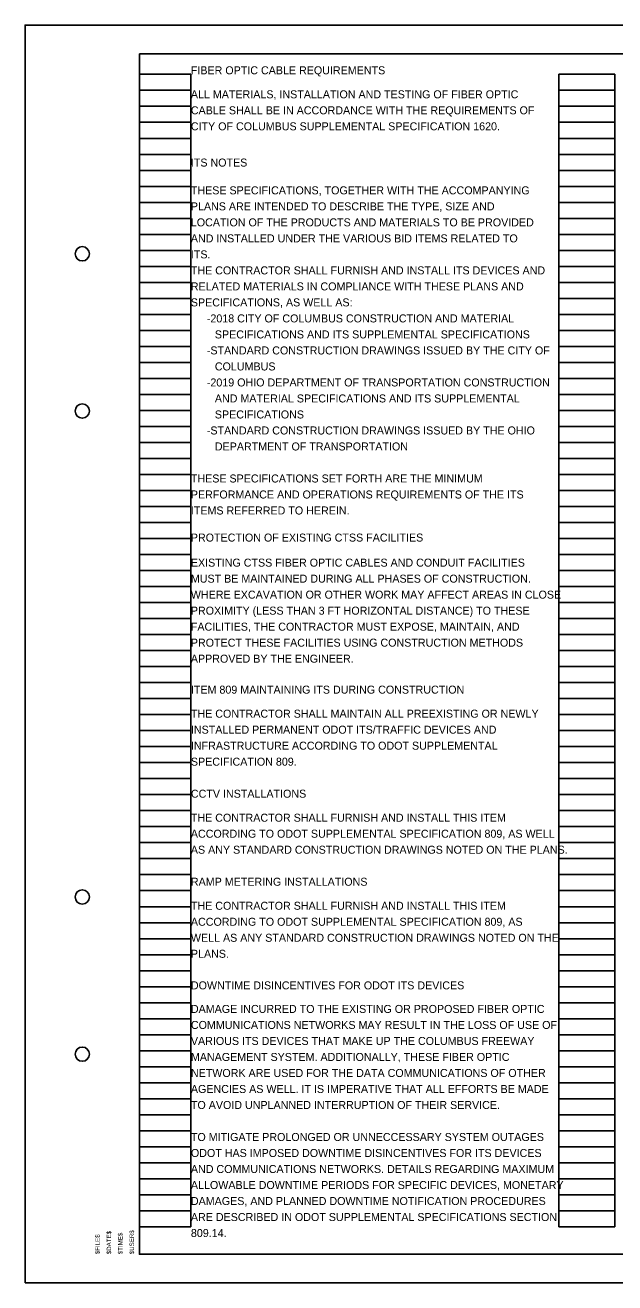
# Model space of a CAD drawing. Extents: x -36.9 to 49.6, y -47.1 to 37.
# Drawn here: x -0.51 to 9.81, y -7.51 to 14.49 of the extents above; entities that cross this region are included whole.
import ezdxf

# ---------------------------------------------------------------- set-up
doc = ezdxf.new("R2010")
doc.units = 0
for name, color, linetype in [('PF_P_Text', 7, 'Continuous'), ('SC_Scratch1', 7, 'Continuous'), ('SH_Cut_Line', 7, 'Continuous'), ('SH_Text', 7, 'Continuous'), ('TX_P_Misc', 7, 'Continuous')]:
    doc.layers.add(name, color=color, linetype=linetype)

msp = doc.modelspace()

# ---------------------------------------------------------------- linework, layer by layer
at = {"layer": 'PF_P_Text'}
msp.add_lwpolyline([(1.494, 13.992), (32.994, 13.992), (32.994, -7.008), (1.494, -7.008)], close=True, dxfattribs=at)
for centre in [(0.494, 10.492), (0.494, 7.742), (0.494, -0.758), (0.494, -3.508)]:
    msp.add_circle(centre, 0.125, dxfattribs=at)
at = {"layer": 'SC_Scratch1'}
for p, q in [((1.494, -6.528), (1.494, 13.632)), ((1.494, 13.632), (2.394, 13.632)), ((2.394, -6.528), (2.394, 13.632)), ((8.834, -6.528), (8.834, 13.632)), ((8.834, 13.632), (9.814, 13.632)), ((9.814, -6.528), (9.814, 13.632)), ((1.494, 13.352), (2.394, 13.352)), ((8.834, 13.352), (9.814, 13.352)), ((1.494, 13.072), (2.394, 13.072)), ((8.834, 13.072), (9.814, 13.072)), ((1.494, 12.792), (2.394, 12.792)), ((8.834, 12.792), (9.814, 12.792)), ((1.494, 12.512), (2.394, 12.512)), ((8.834, 12.512), (9.814, 12.512)), ((1.494, 12.232), (2.394, 12.232)), ((8.834, 12.232), (9.814, 12.232)), ((1.494, 11.952), (2.394, 11.952)), ((8.834, 11.952), (9.814, 11.952)), ((1.494, 11.672), (2.394, 11.672)), ((8.834, 11.672), (9.814, 11.672)), ((1.494, 11.392), (2.394, 11.392)), ((8.834, 11.392), (9.814, 11.392)), ((1.494, 11.112), (2.394, 11.112)), ((8.834, 11.112), (9.814, 11.112)), ((1.494, 10.832), (2.394, 10.832)), ((8.834, 10.832), (9.814, 10.832)), ((1.494, 10.552), (2.394, 10.552)), ((8.834, 10.552), (9.814, 10.552)), ((1.494, 10.272), (2.394, 10.272)), ((8.834, 10.272), (9.814, 10.272)), ((1.494, 9.992), (2.394, 9.992)), ((8.834, 9.992), (9.814, 9.992)), ((1.494, 9.712), (2.394, 9.712)), ((8.834, 9.712), (9.814, 9.712)), ((1.494, 9.432), (2.394, 9.432)), ((8.834, 9.432), (9.814, 9.432)), ((1.494, 9.152), (2.394, 9.152)), ((8.834, 9.152), (9.814, 9.152)), ((1.494, 8.872), (2.394, 8.872)), ((8.834, 8.872), (9.814, 8.872)), ((1.494, 8.592), (2.394, 8.592)), ((8.834, 8.592), (9.814, 8.592)), ((1.494, 8.312), (2.394, 8.312)), ((8.834, 8.312), (9.814, 8.312)), ((1.494, 8.032), (2.394, 8.032)), ((8.834, 8.032), (9.814, 8.032)), ((1.494, 7.752), (2.394, 7.752)), ((8.834, 7.752), (9.814, 7.752)), ((1.494, 7.472), (2.394, 7.472)), ((8.834, 7.472), (9.814, 7.472)), ((1.494, 7.192), (2.394, 7.192)), ((8.834, 7.192), (9.814, 7.192)), ((1.494, 6.912), (2.394, 6.912)), ((8.834, 6.912), (9.814, 6.912)), ((1.494, 6.632), (2.394, 6.632)), ((8.834, 6.632), (9.814, 6.632)), ((1.494, 6.352), (2.394, 6.352)), ((8.834, 6.352), (9.814, 6.352)), ((1.494, 6.072), (2.394, 6.072)), ((8.834, 6.072), (9.814, 6.072)), ((1.494, 5.792), (2.394, 5.792)), ((8.834, 5.792), (9.814, 5.792)), ((1.494, 5.512), (2.394, 5.512)), ((8.834, 5.512), (9.814, 5.512)), ((1.494, 5.232), (2.394, 5.232)), ((8.834, 5.232), (9.814, 5.232)), ((1.494, 4.952), (2.394, 4.952)), ((8.834, 4.952), (9.814, 4.952)), ((1.494, 4.672), (2.394, 4.672)), ((8.834, 4.672), (9.814, 4.672)), ((1.494, 4.392), (2.394, 4.392)), ((8.834, 4.392), (9.814, 4.392)), ((1.494, 4.112), (2.394, 4.112)), ((8.834, 4.112), (9.814, 4.112)), ((1.494, 3.832), (2.394, 3.832)), ((8.834, 3.832), (9.814, 3.832)), ((1.494, 3.552), (2.394, 3.552)), ((8.834, 3.552), (9.814, 3.552)), ((1.494, 3.272), (2.394, 3.272)), ((8.834, 3.272), (9.814, 3.272)), ((1.494, 2.992), (2.394, 2.992)), ((8.834, 2.992), (9.814, 2.992)), ((1.494, 2.712), (2.394, 2.712)), ((8.834, 2.712), (9.814, 2.712)), ((1.494, 2.432), (2.394, 2.432)), ((8.834, 2.432), (9.814, 2.432)), ((1.494, 2.152), (2.394, 2.152)), ((8.834, 2.152), (9.814, 2.152)), ((1.494, 1.872), (2.394, 1.872)), ((8.834, 1.872), (9.814, 1.872)), ((1.494, 1.592), (2.394, 1.592)), ((8.834, 1.592), (9.814, 1.592)), ((1.494, 1.312), (2.394, 1.312)), ((8.834, 1.312), (9.814, 1.312)), ((1.494, 1.032), (2.394, 1.032)), ((8.834, 1.032), (9.814, 1.032)), ((1.494, 0.752), (2.394, 0.752)), ((8.834, 0.752), (9.814, 0.752)), ((1.494, 0.472), (2.394, 0.472)), ((8.834, 0.472), (9.814, 0.472)), ((1.494, 0.192), (2.394, 0.192)), ((8.834, 0.192), (9.814, 0.192)), ((1.494, -0.088), (2.394, -0.088)), ((8.834, -0.088), (9.814, -0.088)), ((1.494, -0.368), (2.394, -0.368)), ((8.834, -0.368), (9.814, -0.368)), ((1.494, -0.648), (2.394, -0.648)), ((8.834, -0.648), (9.814, -0.648)), ((1.494, -0.928), (2.394, -0.928)), ((8.834, -0.928), (9.814, -0.928)), ((1.494, -1.208), (2.394, -1.208)), ((8.834, -1.208), (9.814, -1.208)), ((1.494, -1.488), (2.394, -1.488)), ((8.834, -1.488), (9.814, -1.488)), ((1.494, -1.768), (2.394, -1.768)), ((8.834, -1.768), (9.814, -1.768)), ((1.494, -2.048), (2.394, -2.048)), ((8.834, -2.048), (9.814, -2.048)), ((1.494, -2.328), (2.394, -2.328)), ((8.834, -2.328), (9.814, -2.328)), ((1.494, -2.608), (2.394, -2.608)), ((8.834, -2.608), (9.814, -2.608)), ((1.494, -2.888), (2.394, -2.888)), ((8.834, -2.888), (9.814, -2.888)), ((1.494, -3.168), (2.394, -3.168)), ((8.834, -3.168), (9.814, -3.168)), ((1.494, -3.448), (2.394, -3.448)), ((8.834, -3.448), (9.814, -3.448)), ((1.494, -3.728), (2.394, -3.728)), ((8.834, -3.728), (9.814, -3.728)), ((1.494, -4.008), (2.394, -4.008)), ((8.834, -4.008), (9.814, -4.008)), ((1.494, -4.288), (2.394, -4.288)), ((8.834, -4.288), (9.814, -4.288)), ((1.494, -4.568), (2.394, -4.568)), ((8.834, -4.568), (9.814, -4.568)), ((1.494, -4.848), (2.394, -4.848)), ((8.834, -4.848), (9.814, -4.848)), ((1.494, -5.128), (2.394, -5.128)), ((8.834, -5.128), (9.814, -5.128)), ((1.494, -5.408), (2.394, -5.408)), ((8.834, -5.408), (9.814, -5.408)), ((1.494, -5.688), (2.394, -5.688)), ((8.834, -5.688), (9.814, -5.688)), ((1.494, -5.968), (2.394, -5.968)), ((8.834, -5.968), (9.814, -5.968)), ((1.494, -6.248), (2.394, -6.248)), ((8.834, -6.248), (9.814, -6.248)), ((1.494, -6.528), (2.394, -6.528)), ((8.834, -6.528), (9.814, -6.528)), ((-0.506, -7.508), (-0.506, -7.508))]:
    msp.add_line(p, q, dxfattribs=at)
at = {"layer": 'SH_Cut_Line'}
msp.add_lwpolyline([(-0.506, -7.508), (33.494, -7.508), (33.494, 14.492), (-0.506, 14.492)], close=True, dxfattribs=at)

# ---------------------------------------------------------------- texts
at = {"layer": 'SH_Text'}
for s, p in [('FIBER OPTIC CABLE REQUIREMENTS', (2.394, 13.632)), ('ALL MATERIALS, INSTALLATION AND TESTING OF FIBER OPTIC ', (2.394, 13.212)), ('CABLE SHALL BE IN ACCORDANCE WITH THE REQUIREMENTS OF ', (2.394, 12.932)), ('CITY OF COLUMBUS SUPPLEMENTAL SPECIFICATION 1620.', (2.394, 12.652)), ('THESE SPECIFICATIONS, TOGETHER WITH THE ACCOMPANYING ', (2.394, 11.532)), ('PLANS ARE INTENDED TO DESCRIBE THE TYPE, SIZE AND ', (2.394, 11.252)), ('LOCATION OF THE PRODUCTS AND MATERIALS TO BE PROVIDED ', (2.394, 10.972)), ('AND INSTALLED UNDER THE VARIOUS BID ITEMS RELATED TO ', (2.394, 10.692)), ('ITS. ', (2.394, 10.412)), ('THE CONTRACTOR SHALL FURNISH AND INSTALL ITS DEVICES AND ', (2.394, 10.132)), ('RELATED MATERIALS IN COMPLIANCE WITH THESE PLANS AND ', (2.394, 9.852)), ('SPECIFICATIONS, AS WELL AS:', (2.394, 9.572)), ('-2018 CITY OF COLUMBUS CONSTRUCTION AND MATERIAL ', (2.674, 9.292)), ('SPECIFICATIONS AND ITS SUPPLEMENTAL SPECIFICATIONS', (2.814, 9.012)), ('-STANDARD CONSTRUCTION DRAWINGS ISSUED BY THE CITY OF ', (2.674, 8.732)), ('COLUMBUS', (2.814, 8.452)), ('-2019 OHIO DEPARTMENT OF TRANSPORTATION CONSTRUCTION ', (2.674, 8.172)), ('AND MATERIAL SPECIFICATIONS AND ITS SUPPLEMENTAL ', (2.814, 7.892)), ('SPECIFICATIONS', (2.814, 7.612)), ('-STANDARD CONSTRUCTION DRAWINGS ISSUED BY THE OHIO ', (2.674, 7.332)), ('DEPARTMENT OF TRANSPORTATION', (2.814, 7.052)), ('THESE SPECIFICATIONS SET FORTH ARE THE MINIMUM ', (2.394, 6.492)), ('PERFORMANCE AND OPERATIONS REQUIREMENTS OF THE ITS ', (2.394, 6.212)), ('ITEMS REFERRED TO HEREIN.', (2.394, 5.932)), ('EXISTING CTSS FIBER OPTIC CABLES AND CONDUIT FACILITIES ', (2.394, 5.02)), ('MUST BE MAINTAINED DURING ALL PHASES OF CONSTRUCTION. ', (2.394, 4.74)), ('WHERE EXCAVATION OR OTHER WORK MAY AFFECT AREAS IN CLOSE ', (2.394, 4.46)), ('PROXIMITY (LESS THAN 3 FT HORIZONTAL DISTANCE) TO THESE ', (2.394, 4.18)), ('FACILITIES, THE CONTRACTOR MUST EXPOSE, MAINTAIN, AND ', (2.394, 3.9)), ('PROTECT THESE FACILITIES USING CONSTRUCTION METHODS ', (2.394, 3.62)), ('APPROVED BY THE ENGINEER.', (2.394, 3.34)), ('THE CONTRACTOR SHALL MAINTAIN ALL PREEXISTING OR NEWLY ', (2.395, 2.378)), ('INSTALLED PERMANENT ODOT ITS/TRAFFIC DEVICES AND ', (2.395, 2.098)), ('INFRASTRUCTURE ACCORDING TO ODOT SUPPLEMENTAL ', (2.395, 1.818)), ('SPECIFICATION 809.', (2.395, 1.538)), ('THE CONTRACTOR SHALL FURNISH AND INSTALL THIS ITEM ', (2.394, 0.558)), ('ACCORDING TO ODOT SUPPLEMENTAL SPECIFICATION 809, AS WELL ', (2.394, 0.278)), ('AS ANY STANDARD CONSTRUCTION DRAWINGS NOTED ON THE PLANS.', (2.394, -0.002)), ('THE CONTRACTOR SHALL FURNISH AND INSTALL THIS ITEM ', (2.395, -0.982)), ('ACCORDING TO ODOT SUPPLEMENTAL SPECIFICATION 809, AS ', (2.395, -1.262)), ('WELL AS ANY STANDARD CONSTRUCTION DRAWINGS NOTED ON THE ', (2.395, -1.542)), ('PLANS.', (2.395, -1.822)), ('DAMAGE INCURRED TO THE EXISTING OR PROPOSED FIBER OPTIC ', (2.395, -2.787)), ('COMMUNICATIONS NETWORKS MAY RESULT IN THE LOSS OF USE OF ', (2.395, -3.067)), ('VARIOUS ITS DEVICES THAT MAKE UP THE COLUMBUS FREEWAY ', (2.395, -3.347)), ('MANAGEMENT SYSTEM. ADDITIONALLY, THESE FIBER OPTIC ', (2.395, -3.627)), ('NETWORK ARE USED FOR THE DATA COMMUNICATIONS OF OTHER ', (2.395, -3.907)), ('AGENCIES AS WELL. IT IS IMPERATIVE THAT ALL EFFORTS BE MADE ', (2.395, -4.187)), ('TO AVOID UNPLANNED INTERRUPTION OF THEIR SERVICE.', (2.395, -4.467)), ('TO MITIGATE PROLONGED OR UNNECCESSARY SYSTEM OUTAGES ', (2.395, -5.027)), ('ODOT HAS IMPOSED DOWNTIME DISINCENTIVES FOR ITS DEVICES ', (2.395, -5.307)), ('AND COMMUNICATIONS NETWORKS. DETAILS REGARDING MAXIMUM ', (2.395, -5.587)), ('ALLOWABLE DOWNTIME PERIODS FOR SPECIFIC DEVICES, MONETARY ', (2.395, -5.867)), ('DAMAGES, AND PLANNED DOWNTIME NOTIFICATION PROCEDURES ', (2.395, -6.147)), ('ARE DESCRIBED IN ODOT SUPPLEMENTAL SPECIFICATIONS SECTION ', (2.395, -6.427)), ('809.14.', (2.395, -6.707))]:
    msp.add_text(s, height=0.14, dxfattribs=at).set_placement(p)
for s, p in [('ITS NOTES', (2.394, 12.018)), ('PROTECTION OF EXISTING CTSS FACILITIES', (2.394, 5.458)), ('ITEM 809 MAINTAINING ITS DURING CONSTRUCTION', (2.395, 2.798)), ('CCTV INSTALLATIONS', (2.395, 0.978)), ('RAMP METERING INSTALLATIONS', (2.395, -0.562)), ('DOWNTIME DISINCENTIVES FOR ODOT ITS DEVICES', (2.395, -2.375))]:
    msp.add_text(s, height=0.14, rotation=0.005, dxfattribs=at).set_placement(p)
at = {"layer": 'TX_P_Misc'}
for s, p in [('$FILE$', (0.799, -7.008)), ('$DATE$', (0.999, -7.008)), ('$TIME$', (1.199, -7.008)), ('$USER$', (1.399, -7.008))]:
    msp.add_text(s, height=0.078, rotation=90, dxfattribs=at).set_placement(p)

doc.saveas('drawing.dxf')
